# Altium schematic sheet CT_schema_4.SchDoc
size 421 x 246 mm
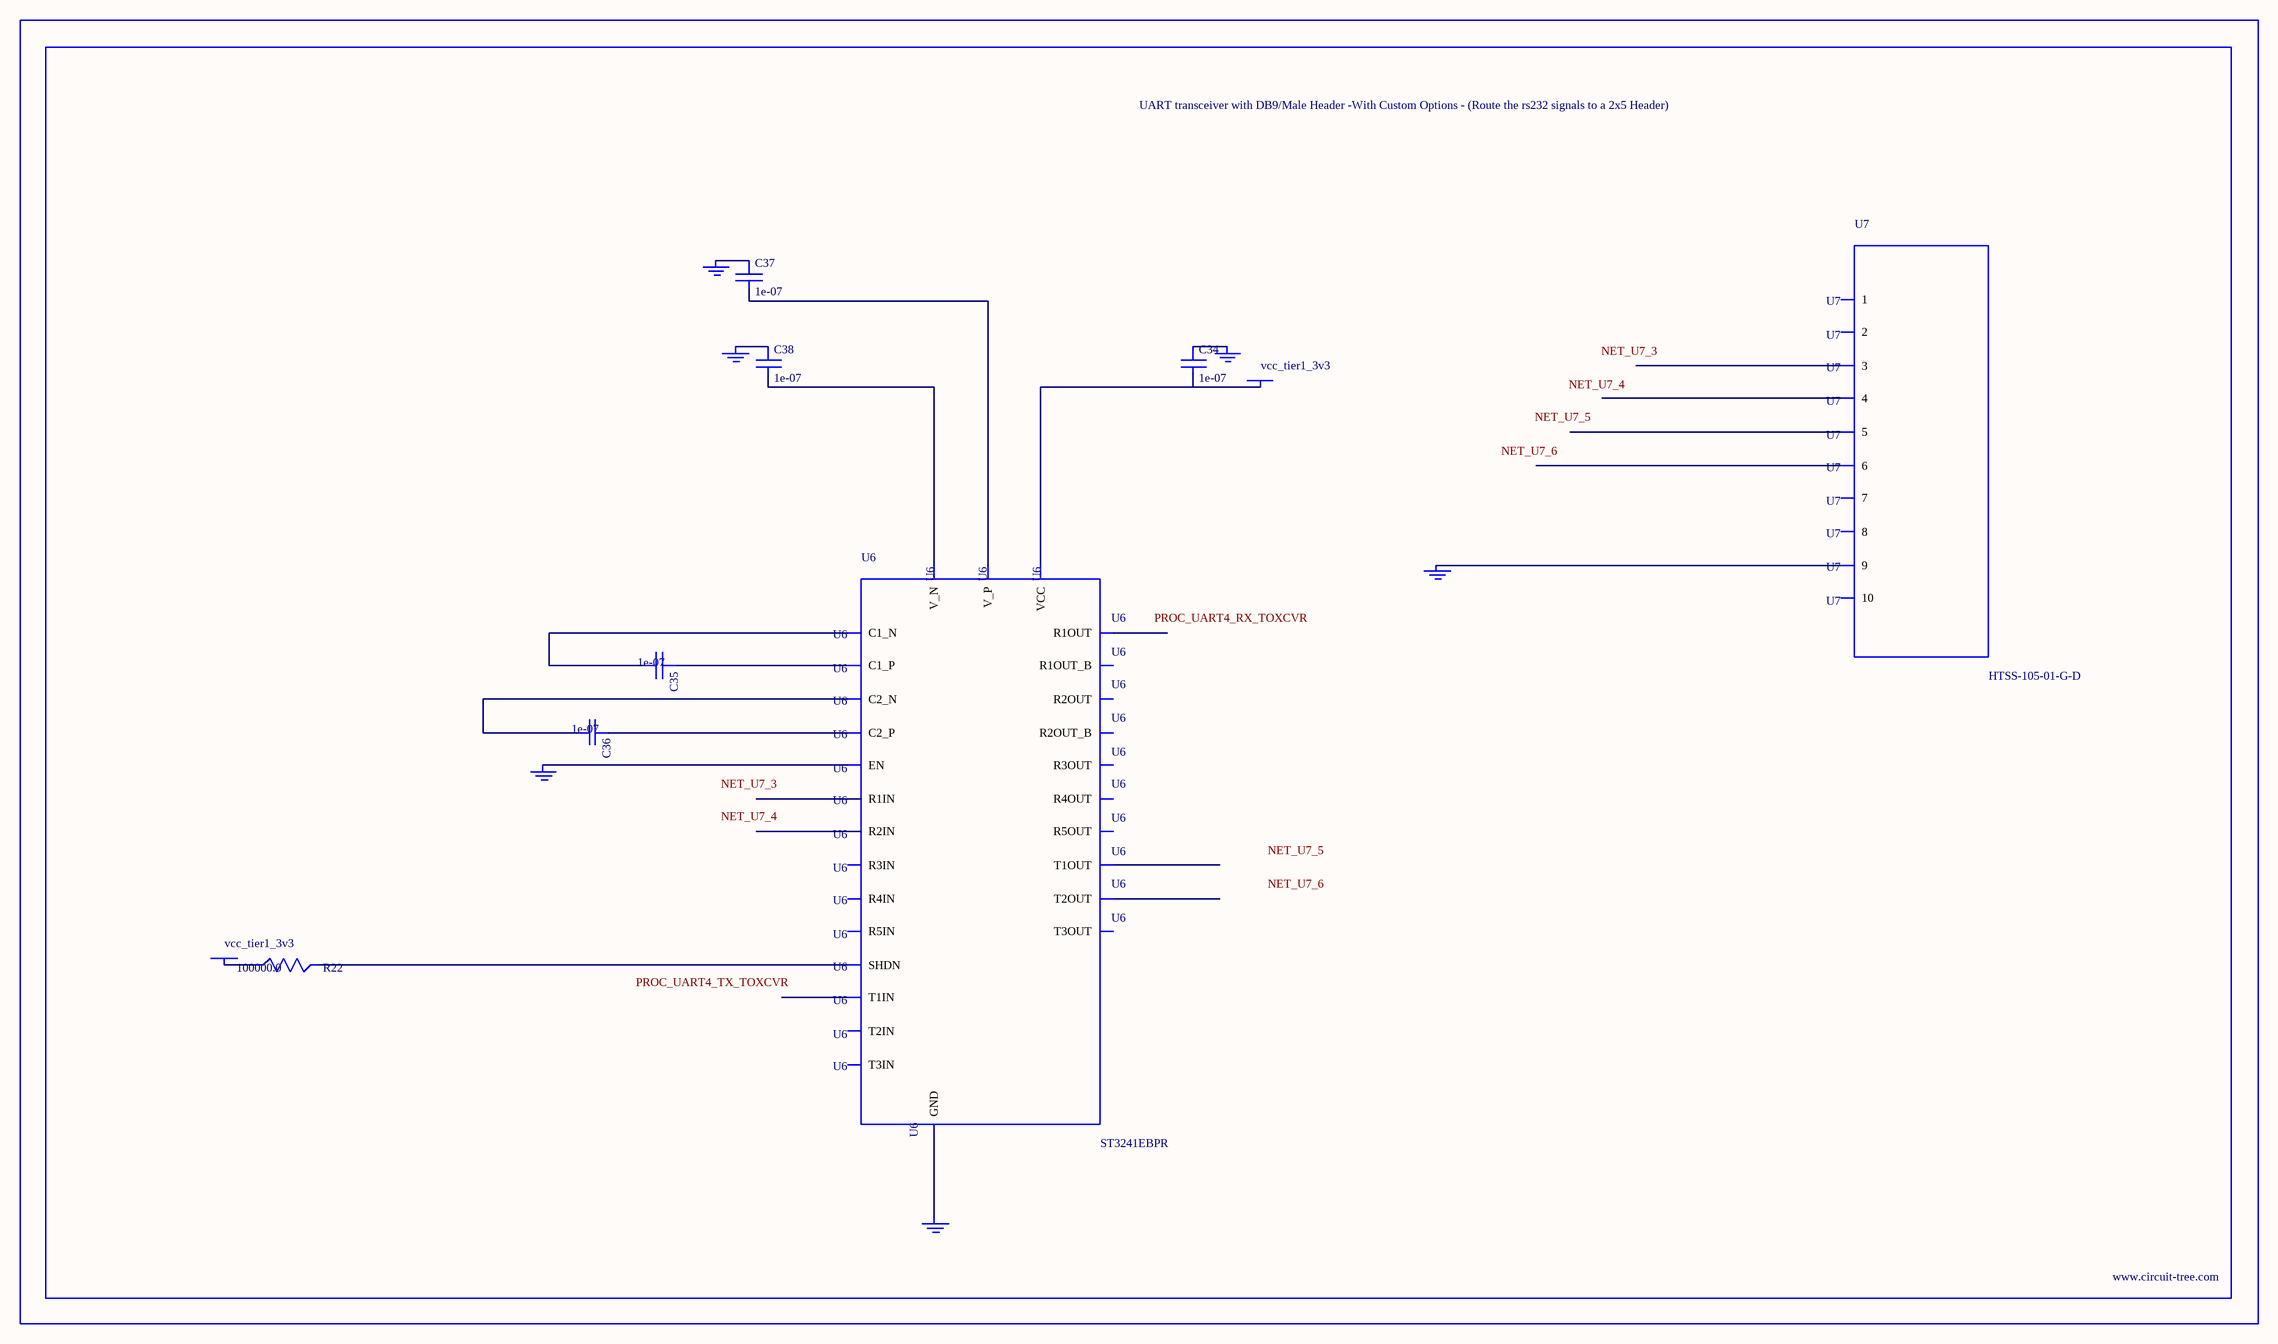
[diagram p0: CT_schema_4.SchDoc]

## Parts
BORDER3  (no value)
C34  1e-07  [C0402]
C35  1e-07  [C0402]
C36  1e-07  [C0402]
C37  1e-07  [C0402]
C38  1e-07  [C0402]
GND_INSTANCE_3_0  (no value)
GND_INSTANCE_3_1  (no value)
GND_INSTANCE_3_2  (no value)
GND_INSTANCE_3_3  (no value)
GND_INSTANCE_3_4  (no value)
GND_INSTANCE_3_5  (no value)
POWER_INSTANCE_3_0  vcc_tier1_3v3
POWER_INSTANCE_3_1  vcc_tier1_3v3
R22  100000.0  [R0603]
U6  ST3241EBPR  [SSOP-28]
U7  HTSS-105-01-G-D  [HTSS-105-01-G-D]

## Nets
NetC34_1: C34.1 GND_INSTANCE_3_2.0(GND)
NetC34_2: C34.2 POWER_INSTANCE_3_1.0(PWR) U6.26(VCC)
NetC35_1: C35.1 U6.28(C1_P)
NetC35_2: C35.2 U6.24(C1_N)
NetC36_1: C36.1 U6.1(C2_P)
NetC36_2: C36.2 U6.2(C2_N)
NetC37_1: C37.1 GND_INSTANCE_3_3.0(GND)
NetC37_2: C37.2 U6.27(V_P)
NetC38_1: C38.1 GND_INSTANCE_3_0.0(GND)
NetC38_2: C38.2 U6.3(V_N)
NetGND_INSTANCE_3_1_0: GND_INSTANCE_3_1.0(GND) U6.23(EN)
NetGND_INSTANCE_3_4_0: GND_INSTANCE_3_4.0(GND) U6.25(GND)
NetGND_INSTANCE_3_5_0: GND_INSTANCE_3_5.0(GND) U7.9
NetPOWER_INSTANCE_3_0_0: POWER_INSTANCE_3_0.0(PWR) R22.1
NetR22_2: R22.2 U6.22(SHDN)

Not connected (* = marked no-connect by the designer): U6 4(R1IN) 5(R2IN) 6(R3IN) 7(R4IN) 8(R5IN) 9(T1OUT) 10(T2OUT) 11(T3OUT) 12(T3IN) 13(T2IN) 14(T1IN) 15(R5OUT) 16(R4OUT) 17(R3OUT) 18(R2OUT) 19(R1OUT) 20(R2OUT_B) 21(R1OUT_B); U7 1 2 3 4 5 6 7 8 10

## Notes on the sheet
- Labels drawn without touching a wire or pin: NET_U7_3, NET_U7_4, NET_U7_5, NET_U7_6, PROC_UART4_RX_TOXCVR, PROC_UART4_TX_TOXCVR

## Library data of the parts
BORDER3 = BORDER_PAGE3
C34-C38 = C0402C104K3RACTU
GND_INSTANCE_3_0-GND_INSTANCE_3_5 = GND
POWER_INSTANCE_3_0 POWER_INSTANCE_3_1 = PWR
R22 = RC0603JR-07100KL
